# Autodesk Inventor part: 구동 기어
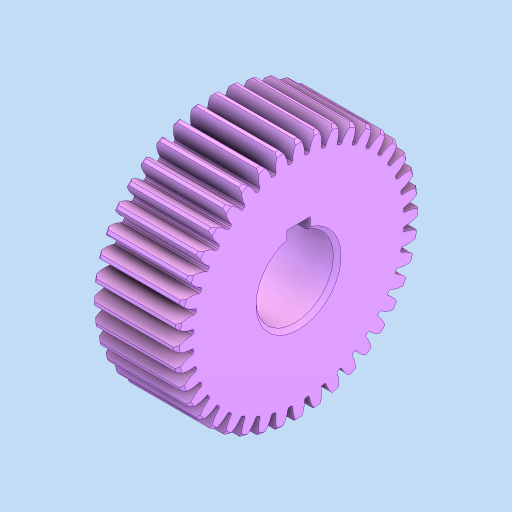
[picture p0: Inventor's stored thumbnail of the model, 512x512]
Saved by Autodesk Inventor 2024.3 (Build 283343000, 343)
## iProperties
Created: 2025-11
Part Number: 구동 기어
Material: 강철, 합금
Document SubType Name: Modeling
Designer: PC2-03
Density: 7.73 g/cm^3
Appearance: 기본값
Author: jhkim
Sending System: Autodesk Inventor 2026
Preprocessor: ST-DEVELOPER v20.1
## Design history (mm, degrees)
feature "솔리드1"
node "솔리드2"
